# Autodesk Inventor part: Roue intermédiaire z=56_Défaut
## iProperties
Shininess: 64.0
Length Units: 11269
Angle Units: 11279
Time Units: 11290
Mass Units: 11283
Length Display Precision: 3
Angle Display Precision: 2
Compacted: True
Part Number: Roue intermédiaire z=56_Défaut
Document SubType Name: Modeling
Created: 2006-01
Material: Par défaut
Designer: riri
Density: 0.0
Volumn: 0.0
Area: 0.0
PropertySet Name: Model Information
Control State: 0
Master: False
Checked Out: False
Author: riri
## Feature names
1. Base1
